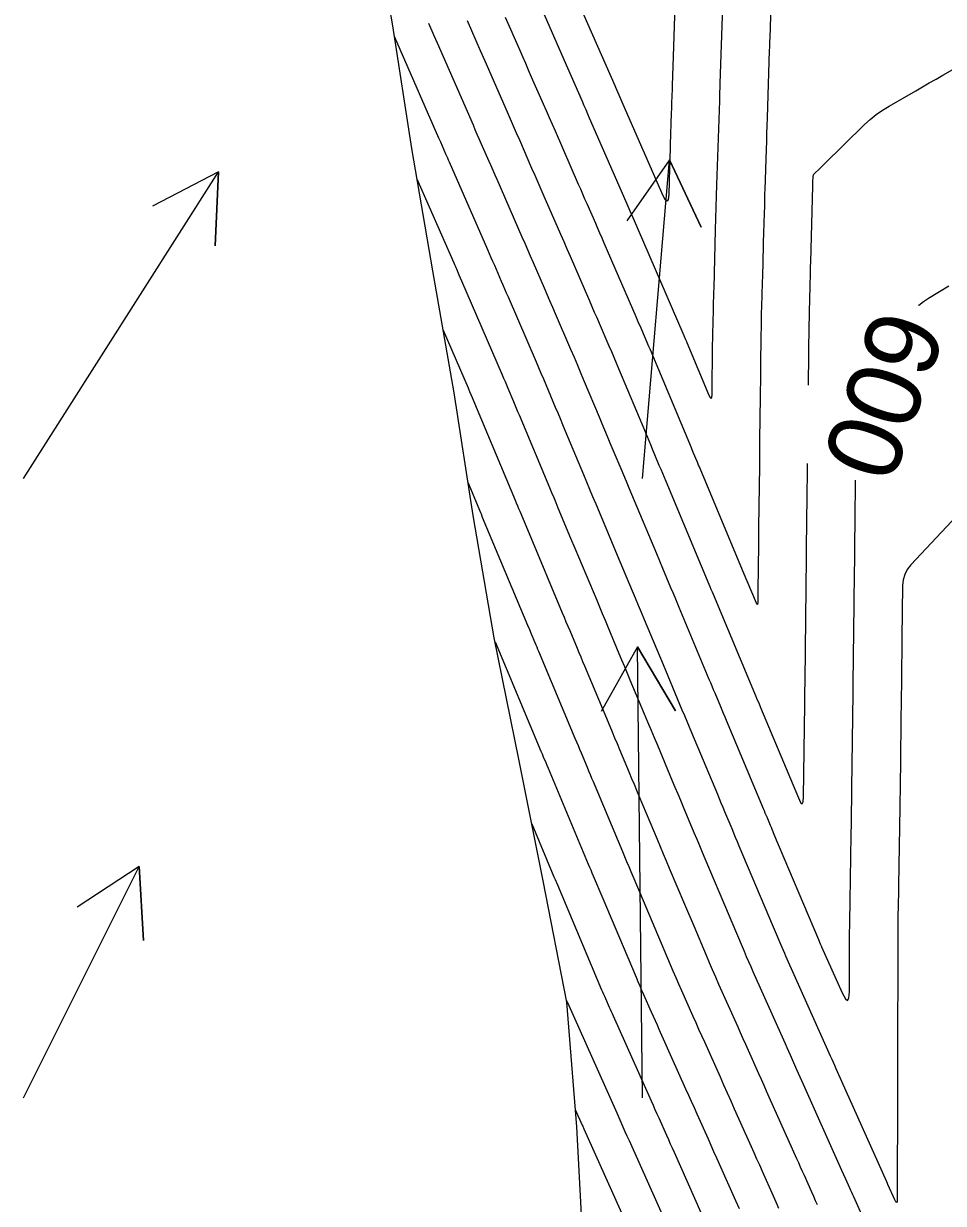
# Model space of a CAD drawing. Extents: x 954385 to 988206, y 1868364 to 1924553.
# Drawn here: x 957957.1 to 958031.4, y 1918710.4 to 1918805.7 of the extents above; entities that cross this region are included whole.
import ezdxf

# ---------------------------------------------------------------- set-up
doc = ezdxf.new("R2010")
doc.units = 0
for name, color, linetype in [('24', 7, 'Continuous'), ('26', 7, 'Continuous'), ('5', 7, 'Continuous'), ('6', 7, 'Continuous'), ('7', 7, 'Continuous')]:
    doc.layers.add(name, color=color, linetype=linetype)

msp = doc.modelspace()

# ---------------------------------------------------------------- linework, layer by layer
at = {"layer": '24'}
msp.add_lwpolyline([(958002.36, 1918706.439), (958001.804, 1918716.563), (958001.002, 1918726.632), (957999.088, 1918736.451), (957997.137, 1918746.262), (957995.151, 1918756.065), (957993.448, 1918765.931), (957991.903, 1918775.833), (957990.175, 1918785.694), (957988.49, 1918795.565), (957986.956, 1918805.469), (957985.254, 1918815.336), (957982.15, 1918824.888), (957981.062, 1918828.744), (957980.363, 1918834.736), (957977.937, 1918844.44), (957974.671, 1918853.956), (957971.691, 1918863.536)], dxfattribs=at)
at = {"layer": '26'}
for points in [[(958007.131, 1918768.928), (958009.293, 1918794.663), (958011.848, 1918789.234), (958009.293, 1918794.663), (958005.869, 1918789.736)], [(957957.131, 1918768.928), (957972.862, 1918793.705), (957972.609, 1918787.71), (957972.862, 1918793.705), (957967.544, 1918790.926)], [(958007.131, 1918718.928), (958006.723, 1918755.342), (958009.781, 1918750.18), (958006.723, 1918755.342), (958003.781, 1918750.112)], [(957957.131, 1918718.928), (957966.462, 1918737.61), (957966.824, 1918731.621), (957966.462, 1918737.61), (957961.457, 1918734.302)]]:
    msp.add_lwpolyline(points, dxfattribs=at)
at = {"layer": '6'}
for points in [[(957989.838, 1918805.686), (957990.266, 1918804.707), (957990.523, 1918804.12), (957993.431, 1918797.475), (957993.591, 1918797.11), (957993.75, 1918796.745), (957993.91, 1918796.38), (957994.07, 1918796.015), (957994.708, 1918794.555), (957994.868, 1918794.19), (957995.028, 1918793.825), (957995.188, 1918793.46), (957995.347, 1918793.095), (957997.384, 1918788.442), (957997.609, 1918787.927), (957997.834, 1918787.413), (957998.057, 1918786.898), (957998.281, 1918786.382), (957999.173, 1918784.321), (957999.396, 1918783.806), (957999.619, 1918783.291), (957999.842, 1918782.775), (958000.064, 1918782.26), (958001.316, 1918779.367), (958001.595, 1918778.719), (958001.872, 1918778.07), (958002.148, 1918777.42), (958002.422, 1918776.769), (958003.623, 1918773.902), (958003.841, 1918773.382), (958004.059, 1918772.862), (958004.277, 1918772.342), (958004.495, 1918771.822), (958005.366, 1918769.743), (958005.584, 1918769.223), (958005.801, 1918768.703), (958006.019, 1918768.183), (958006.237, 1918767.663), (958008.244, 1918762.868), (958008.737, 1918761.69), (958009.395, 1918760.12), (958009.559, 1918759.728), (958009.724, 1918759.335), (958009.888, 1918758.943), (958010.052, 1918758.55), (958012.49, 1918752.728), (958012.606, 1918752.452), (958012.722, 1918752.176), (958012.837, 1918751.9), (958012.953, 1918751.624), (958013.416, 1918750.519), (958013.532, 1918750.243), (958013.647, 1918749.967), (958013.763, 1918749.691), (958013.879, 1918749.415), (958016.87, 1918742.276), (958016.94, 1918742.108), (958017.011, 1918741.94), (958017.081, 1918741.773), (958017.151, 1918741.605), (958017.432, 1918740.934), (958017.503, 1918740.766), (958017.573, 1918740.599), (958017.644, 1918740.431), (958017.714, 1918740.264), (958021.331, 1918731.715), (958021.482, 1918731.358), (958021.508, 1918731.298), (958021.533, 1918731.239), (958021.559, 1918731.18), (958021.585, 1918731.121), (958023.254, 1918727.387), (958023.505, 1918726.913), (958023.685, 1918726.775), (958023.793, 1918726.974), (958023.831, 1918727.509), (958023.841, 1918731.38), (958023.841, 1918731.569), (958023.843, 1918731.757), (958023.845, 1918731.946), (958023.848, 1918732.134), (958023.862, 1918732.954), (958023.864, 1918733.109), (958023.867, 1918733.265), (958023.869, 1918733.421), (958023.872, 1918733.577), (958023.885, 1918734.356), (958023.89, 1918734.667), (958023.893, 1918734.823), (958023.982, 1918740.161), (958023.997, 1918741.103), (958024.011, 1918742.044), (958024.024, 1918742.986), (958024.036, 1918743.927), (958024.129, 1918751.585), (958024.136, 1918752.166), (958024.138, 1918752.343), (958024.138, 1918752.365), (958024.214, 1918758.741), (958024.218, 1918759.127), (958024.223, 1918759.512), (958024.227, 1918759.898), (958024.232, 1918760.283), (958024.268, 1918763.368), (958024.297, 1918765.809), (958024.303, 1918766.345), (958024.309, 1918766.88), (958024.315, 1918767.416), (958024.322, 1918767.951), (958024.332, 1918768.784)], [(958029.404, 1918782.901), (958029.447, 1918782.938), (958029.828, 1918783.225), (958030.23, 1918783.488), (958031.876, 1918784.488)], [(957995.217, 1918755.74), (957998.918, 1918746.911), (957999.013, 1918746.683), (957999.109, 1918746.455), (957999.3, 1918745.999), (957999.395, 1918745.771), (957999.491, 1918745.543), (958002.743, 1918737.778), (958002.84, 1918737.546), (958002.938, 1918737.315), (958003.035, 1918737.083), (958003.133, 1918736.852), (958003.916, 1918735.002), (958006.6, 1918728.657), (958006.75, 1918728.306), (958006.901, 1918727.956), (958007.053, 1918727.607), (958007.208, 1918727.259), (958007.83, 1918725.867), (958007.985, 1918725.519), (958008.141, 1918725.171), (958008.296, 1918724.823), (958008.452, 1918724.475), (958010.605, 1918719.651), (958010.831, 1918719.145), (958011.057, 1918718.639), (958011.283, 1918718.133), (958011.509, 1918717.627), (958012.414, 1918715.603), (958012.64, 1918715.097), (958012.866, 1918714.591), (958013.092, 1918714.085), (958013.318, 1918713.579), (958014.64, 1918710.621), (958014.93, 1918709.973)]]:
    msp.add_lwpolyline(points, dxfattribs=at)
at = {"layer": '7'}
for points in [[(958009.811, 1918809.565), (958009.598, 1918803.001), (958009.521, 1918800.652), (958009.509, 1918800.281), (958009.497, 1918799.91), (958009.473, 1918799.169), (958009.461, 1918798.798), (958009.449, 1918798.427), (958009.367, 1918795.907), (958009.351, 1918795.426), (958009.336, 1918794.944), (958009.32, 1918794.462), (958009.304, 1918793.981), (958009.235, 1918791.851), (958009.194, 1918791.458), (958009.106, 1918791.313), (958008.971, 1918791.415), (958008.788, 1918791.765), (958005.569, 1918799.122), (958005.404, 1918799.498), (958004.966, 1918800.501), (958004.911, 1918800.626), (958001.612, 1918808.165)], [(958017.511, 1918808.051), (958017.395, 1918804.48), (958017.387, 1918804.235), (958017.379, 1918803.991), (958017.371, 1918803.746), (958017.363, 1918803.501), (958017.185, 1918798.045), (958017.165, 1918797.411), (958017.144, 1918796.778), (958017.124, 1918796.144), (958017.103, 1918795.511), (958016.997, 1918792.249), (958016.989, 1918791.979), (958016.98, 1918791.71), (958016.972, 1918791.44), (958016.965, 1918791.171), (958016.936, 1918790.092), (958016.928, 1918789.823), (958016.921, 1918789.553), (958016.914, 1918789.284), (958016.906, 1918789.014), (958016.802, 1918785.205), (958016.792, 1918784.824), (958016.781, 1918784.444), (958016.771, 1918784.063), (958016.761, 1918783.682), (958016.719, 1918782.159), (958016.709, 1918781.778), (958016.701, 1918781.397), (958016.694, 1918781.016), (958016.689, 1918780.636), (958016.655, 1918777.856), (958016.648, 1918777.266), (958016.641, 1918776.676), (958016.634, 1918776.085), (958016.627, 1918775.495), (958016.585, 1918772.075), (958016.579, 1918771.598), (958016.574, 1918771.121), (958016.568, 1918770.643), (958016.562, 1918770.166), (958016.538, 1918768.041), (958016.533, 1918767.672), (958016.529, 1918767.302), (958016.525, 1918766.933), (958016.52, 1918766.563), (958016.503, 1918765.085), (958016.499, 1918764.715), (958016.494, 1918764.346), (958016.49, 1918763.976), (958016.486, 1918763.606), (958016.441, 1918759.895), (958016.438, 1918759.641), (958016.435, 1918759.386), (958016.429, 1918758.878), (958016.422, 1918758.781), (958016.403, 1918758.746), (958016.371, 1918758.771), (958016.328, 1918758.858), (958015.588, 1918760.625), (958015.479, 1918760.885), (958011.772, 1918769.742), (958011.714, 1918769.879), (958011.656, 1918770.017), (958011.599, 1918770.155), (958011.541, 1918770.292), (958011.253, 1918770.98), (958011.137, 1918771.255), (958011.08, 1918771.393), (958007.948, 1918778.866), (958007.839, 1918779.125), (958007.729, 1918779.385), (958007.618, 1918779.644), (958007.507, 1918779.902), (958007.06, 1918780.937), (958006.948, 1918781.195), (958006.836, 1918781.454), (958006.724, 1918781.712), (958006.612, 1918781.971), (958004.031, 1918787.935), (958003.859, 1918788.331), (958003.688, 1918788.726), (958003.515, 1918789.122), (958003.342, 1918789.517), (958002.65, 1918791.098), (958002.477, 1918791.494), (958002.304, 1918791.889), (958002.131, 1918792.284), (958001.958, 1918792.68), (958000.084, 1918796.963), (957999.844, 1918797.511), (957999.605, 1918798.059), (957999.365, 1918798.607), (957999.125, 1918799.155), (957998.166, 1918801.347), (957997.926, 1918801.895), (957997.686, 1918802.443), (957997.446, 1918802.991), (957997.206, 1918803.539), (957996.062, 1918806.154)], [(957998.875, 1918807.072), (958001.059, 1918802.083), (958001.353, 1918801.409), (958001.648, 1918800.736), (958002.237, 1918799.389), (958002.385, 1918799.052), (958002.532, 1918798.716), (958002.679, 1918798.379), (958002.827, 1918798.042), (958005.774, 1918791.305), (958005.858, 1918791.113), (958005.942, 1918790.921), (958006.026, 1918790.729), (958006.111, 1918790.537), (958006.447, 1918789.768), (958006.531, 1918789.576), (958006.615, 1918789.383), (958006.698, 1918789.191), (958006.782, 1918788.999), (958010.391, 1918780.659), (958010.471, 1918780.474), (958010.604, 1918780.166), (958010.631, 1918780.104), (958010.657, 1918780.042), (958010.684, 1918779.98), (958010.71, 1918779.918), (958012.49, 1918775.67), (958012.596, 1918775.458), (958012.672, 1918775.396), (958012.719, 1918775.482), (958012.737, 1918775.718), (958012.752, 1918776.959), (958012.756, 1918777.269), (958012.76, 1918777.579), (958012.764, 1918777.889), (958012.767, 1918778.199), (958012.787, 1918779.786), (958012.792, 1918780.154), (958012.799, 1918780.522), (958012.807, 1918780.89), (958012.816, 1918781.258), (958012.858, 1918782.807), (958012.869, 1918783.188), (958012.879, 1918783.568), (958012.889, 1918783.949), (958012.9, 1918784.33), (958013.027, 1918789.017), (958013.053, 1918789.926), (958013.079, 1918790.834), (958013.107, 1918791.742), (958013.136, 1918792.65), (958013.355, 1918799.414), (958013.372, 1918799.933), (958013.396, 1918800.654), (958013.401, 1918800.822), (958013.604, 1918807.033)], [(957992.95, 1918805.92), (957993.663, 1918804.292), (957994.019, 1918803.477), (957994.375, 1918802.663), (957996.18, 1918798.538), (957996.429, 1918797.97), (957996.677, 1918797.402), (957996.926, 1918796.834), (957997.175, 1918796.266), (957998.169, 1918793.993), (957998.417, 1918793.425), (957998.666, 1918792.857), (957998.915, 1918792.289), (957999.163, 1918791.721), (958000.238, 1918789.267), (958000.499, 1918788.668), (958000.76, 1918788.069), (958001.021, 1918787.47), (958001.28, 1918786.871), (958002.833, 1918783.283), (958003.03, 1918782.828), (958003.227, 1918782.372), (958003.424, 1918781.917), (958003.621, 1918781.461), (958004.409, 1918779.639), (958004.606, 1918779.184), (958004.801, 1918778.727), (958004.994, 1918778.27), (958005.187, 1918777.813), (958007.352, 1918772.647), (958007.489, 1918772.319), (958007.627, 1918771.99), (958007.765, 1918771.661), (958007.903, 1918771.332), (958008.453, 1918770.018), (958008.591, 1918769.689), (958008.729, 1918769.36), (958008.867, 1918769.031), (958009.004, 1918768.703), (958011.867, 1918761.865), (958012.477, 1918760.408), (958012.564, 1918760.2), (958012.651, 1918759.992), (958012.738, 1918759.784), (958012.825, 1918759.576), (958016.17, 1918751.587), (958016.251, 1918751.395), (958016.332, 1918751.202), (958016.534, 1918750.72), (958016.655, 1918750.431), (958019.712, 1918743.136), (958019.892, 1918742.774), (958020.023, 1918742.667), (958020.104, 1918742.815), (958020.135, 1918743.218), (958020.225, 1918750.666), (958020.229, 1918750.978), (958020.234, 1918751.368), (958020.235, 1918751.523), (958020.236, 1918751.601), (958020.248, 1918752.579), (958020.337, 1918760.107), (958020.347, 1918760.914), (958020.356, 1918761.721), (958020.366, 1918762.528), (958020.375, 1918763.335), (958020.424, 1918767.494), (958020.432, 1918768.178), (958020.44, 1918768.863), (958020.455, 1918770.152)], [(958020.531, 1918776.453), (958020.591, 1918781.443), (958020.597, 1918781.858), (958020.605, 1918782.273), (958020.614, 1918782.688), (958020.624, 1918783.104), (958020.669, 1918784.764), (958020.681, 1918785.179), (958020.692, 1918785.595), (958020.703, 1918786.01), (958020.715, 1918786.425), (958020.88, 1918792.521), (958020.881, 1918792.553), (958020.882, 1918792.586), (958020.883, 1918792.618), (958020.884, 1918792.651), (958020.893, 1918792.91), (958020.905, 1918793.297), (958020.914, 1918793.369), (958020.936, 1918793.436), (958020.971, 1918793.497), (958021.018, 1918793.553), (958021.412, 1918793.938), (958021.579, 1918794.102), (958021.747, 1918794.265), (958025.06, 1918797.506), (958025.518, 1918797.927), (958026.001, 1918798.317), (958026.507, 1918798.675), (958027.037, 1918799.002), (958029.205, 1918800.245), (958029.747, 1918800.556), (958030.289, 1918800.866), (958030.831, 1918801.177), (958031.373, 1918801.488), (958037.89, 1918805.224)], [(958032.523, 1918765.905), (958028.798, 1918761.954), (958028.507, 1918761.586), (958028.298, 1918761.185), (958028.171, 1918760.752), (958028.124, 1918760.286), (958028.075, 1918756.046), (958028.071, 1918755.761), (958028.068, 1918755.476), (958028.064, 1918755.191), (958028.061, 1918754.906), (958028.048, 1918753.766), (958028.044, 1918753.481), (958028.041, 1918753.197), (958028.037, 1918752.912), (958028.034, 1918752.627), (958027.994, 1918749.382), (958027.986, 1918748.746), (958027.979, 1918748.11), (958027.971, 1918747.474), (958027.963, 1918746.838), (958027.922, 1918743.461), (958027.919, 1918743.191), (958027.915, 1918742.92), (958027.911, 1918742.649), (958027.907, 1918742.379), (958027.802, 1918736.076), (958027.791, 1918735.388), (958027.779, 1918734.699), (958027.756, 1918733.322), (958027.751, 1918732.977), (958027.747, 1918732.633), (958027.744, 1918732.289), (958027.743, 1918731.944), (958027.717, 1918721.437), (958027.712, 1918719.555), (958027.711, 1918719.085), (958027.71, 1918718.614), (958027.709, 1918718.144), (958027.707, 1918717.673), (958027.694, 1918712.593), (958027.694, 1918712.359), (958027.693, 1918712.124), (958027.693, 1918711.89), (958027.692, 1918711.655), (958027.69, 1918710.714), (958027.678, 1918710.537), (958027.642, 1918710.471), (958027.582, 1918710.516), (958027.499, 1918710.674), (958026.944, 1918711.917), (958026.912, 1918711.988), (958026.848, 1918712.132), (958022.879, 1918721.016), (958022.767, 1918721.267), (958022.655, 1918721.517), (958022.431, 1918722.018), (958022.319, 1918722.269), (958022.207, 1918722.52), (958018.814, 1918730.116), (958018.71, 1918730.349), (958018.608, 1918730.583), (958018.507, 1918730.818), (958018.406, 1918731.053), (958017.71, 1918732.7), (958014.938, 1918739.252), (958014.792, 1918739.597), (958014.646, 1918739.942), (958014.501, 1918740.288), (958014.356, 1918740.633), (958013.777, 1918742.015), (958013.632, 1918742.361), (958013.488, 1918742.707), (958013.343, 1918743.052), (958013.198, 1918743.398), (958011.103, 1918748.399), (958010.912, 1918748.854), (958010.72, 1918749.31), (958010.529, 1918749.766), (958010.338, 1918750.222), (958009.574, 1918752.045), (958009.383, 1918752.501), (958009.192, 1918752.957), (958009.001, 1918753.413), (958008.81, 1918753.869), (958007.279, 1918757.524), (958007.038, 1918758.101), (958006.796, 1918758.678), (958006.555, 1918759.255), (958006.313, 1918759.832), (958005.105, 1918762.717), (958004.38, 1918764.448), (958003.372, 1918766.858), (958003.123, 1918767.452), (958002.874, 1918768.046), (958002.625, 1918768.64), (958002.376, 1918769.234), (958000.877, 1918772.814), (958000.684, 1918773.274), (958000.491, 1918773.734), (958000.298, 1918774.194), (958000.106, 1918774.654), (957999.334, 1918776.494), (957999.141, 1918776.954), (957998.946, 1918777.413), (957998.75, 1918777.872), (957998.553, 1918778.33), (957996.286, 1918783.572), (957996.148, 1918783.891), (957996.01, 1918784.209), (957995.872, 1918784.527), (957995.735, 1918784.846), (957995.183, 1918786.119), (957995.045, 1918786.438), (957994.907, 1918786.756), (957994.768, 1918787.074), (957994.629, 1918787.392), (957991.531, 1918794.47), (957991.46, 1918794.632), (957991.39, 1918794.793), (957991.319, 1918794.955), (957991.248, 1918795.117), (957990.965, 1918795.765), (957990.823, 1918796.088), (957990.681, 1918796.412), (957987.086, 1918804.628)], [(957988.907, 1918793.121), (957991.875, 1918786.342), (957991.928, 1918786.221), (957991.981, 1918786.099), (957992.033, 1918785.978), (957992.086, 1918785.856), (957992.296, 1918785.37), (957992.401, 1918785.127), (957992.507, 1918784.884), (957995.79, 1918777.293), (957995.905, 1918777.025), (957996.02, 1918776.757), (957996.134, 1918776.488), (957996.247, 1918776.22), (957996.698, 1918775.144), (957996.81, 1918774.875), (957996.923, 1918774.606), (957997.036, 1918774.337), (957997.148, 1918774.068), (957999.604, 1918768.208), (957999.775, 1918767.799), (957999.947, 1918767.389), (958000.118, 1918766.98), (958000.29, 1918766.57), (958001.318, 1918764.113), (958001.661, 1918763.294), (958003.42, 1918759.092), (958003.645, 1918758.557), (958003.869, 1918758.021), (958004.093, 1918757.486), (958004.317, 1918756.951), (958005.214, 1918754.809), (958005.438, 1918754.274), (958005.662, 1918753.739), (958005.887, 1918753.203), (958006.111, 1918752.668), (958007.261, 1918749.925), (958007.527, 1918749.289), (958007.794, 1918748.653), (958008.06, 1918748.018), (958008.326, 1918747.382), (958009.526, 1918744.519), (958009.745, 1918743.996), (958009.965, 1918743.473), (958010.184, 1918742.949), (958010.403, 1918742.426), (958011.28, 1918740.332), (958011.499, 1918739.809), (958011.719, 1918739.285), (958011.94, 1918738.763), (958012.161, 1918738.24), (958014.113, 1918733.626), (958014.635, 1918732.392), (958015.331, 1918730.748), (958015.506, 1918730.337), (958015.683, 1918729.927), (958015.862, 1918729.518), (958016.043, 1918729.11), (958018.508, 1918723.591), (958018.641, 1918723.292), (958018.775, 1918722.994), (958018.908, 1918722.696), (958019.041, 1918722.398), (958019.573, 1918721.206), (958019.706, 1918720.908), (958019.839, 1918720.61), (958019.973, 1918720.312), (958020.106, 1918720.014), (958023.205, 1918713.076), (958023.365, 1918712.72), (958023.524, 1918712.364), (958023.842, 1918711.652), (958023.921, 1918711.474), (958024.001, 1918711.296), (958024.08, 1918711.117), (958024.16, 1918710.939), (958027.83, 1918702.717)], [(957991.013, 1918780.913), (957993.027, 1918776.255), (957993.061, 1918776.178), (957993.094, 1918776.1), (957993.127, 1918776.023), (957993.16, 1918775.945), (957993.355, 1918775.478), (957993.42, 1918775.322), (957996.831, 1918767.182), (957996.925, 1918766.957), (957997.019, 1918766.732), (957997.114, 1918766.507), (957997.208, 1918766.282), (957997.962, 1918764.482), (958000.644, 1918758.076), (958000.793, 1918757.72), (958000.941, 1918757.364), (958001.09, 1918757.009), (958001.239, 1918756.653), (958001.835, 1918755.231), (958001.984, 1918754.875), (958002.133, 1918754.52), (958002.282, 1918754.164), (958002.431, 1918753.809), (958004.473, 1918748.936), (958004.67, 1918748.466), (958004.867, 1918747.997), (958005.064, 1918747.527), (958005.26, 1918747.057), (958006.048, 1918745.178), (958006.245, 1918744.708), (958006.441, 1918744.239), (958006.638, 1918743.769), (958006.835, 1918743.299), (958008.302, 1918739.796), (958008.547, 1918739.212), (958008.792, 1918738.629), (958009.038, 1918738.045), (958009.285, 1918737.462), (958010.518, 1918734.548), (958011.258, 1918732.799), (958012.255, 1918730.443), (958012.504, 1918729.856), (958012.757, 1918729.271), (958013.013, 1918728.687), (958013.271, 1918728.105), (958014.809, 1918724.662), (958015.02, 1918724.191), (958015.23, 1918723.72), (958015.44, 1918723.249), (958015.65, 1918722.778), (958016.491, 1918720.895), (958016.702, 1918720.424), (958016.912, 1918719.953), (958017.122, 1918719.482), (958017.333, 1918719.011), (958019.563, 1918714.02), (958019.714, 1918713.682), (958019.865, 1918713.344), (958020.016, 1918713.005), (958020.167, 1918712.667), (958020.772, 1918711.315), (958020.923, 1918710.977), (958021.074, 1918710.639), (958021.225, 1918710.3)], [(958018.146, 1918709.982), (958017.924, 1918710.48), (958017.701, 1918710.978), (958016.811, 1918712.971), (958016.588, 1918713.469), (958016.366, 1918713.967), (958016.143, 1918714.466), (958015.92, 1918714.964), (958014.56, 1918718.009), (958014.272, 1918718.653), (958013.985, 1918719.296), (958013.697, 1918719.94), (958013.41, 1918720.583), (958012.151, 1918723.404), (958011.918, 1918723.925), (958011.685, 1918724.445), (958011.453, 1918724.966), (958011.22, 1918725.487), (958010.29, 1918727.57), (958010.058, 1918728.091), (958009.829, 1918728.614), (958009.603, 1918729.138), (958009.38, 1918729.662), (958007.414, 1918734.308), (958006.898, 1918735.529), (958006.209, 1918737.157), (958006.037, 1918737.564), (958005.865, 1918737.972), (958005.694, 1918738.379), (958005.523, 1918738.787), (958003.163, 1918744.421), (958003.041, 1918744.713), (958002.918, 1918745.005), (958002.796, 1918745.297), (958002.674, 1918745.589), (958002.185, 1918746.756), (958002.062, 1918747.048), (958001.94, 1918747.34), (958001.818, 1918747.632), (958001.695, 1918747.924), (957998.75, 1918754.949), (957998.677, 1918755.125), (957998.603, 1918755.301), (957998.529, 1918755.477), (957998.456, 1918755.653), (957998.161, 1918756.356), (957998.014, 1918756.707), (957997.867, 1918757.059), (957994.211, 1918765.791), (957994.109, 1918766.035), (957994.058, 1918766.157), (957993.03, 1918768.611)], [(957998.176, 1918741.036), (957999.964, 1918736.769), (957999.987, 1918736.713), (958000.01, 1918736.658), (958000.034, 1918736.603), (958000.057, 1918736.547), (958000.244, 1918736.104), (958003.821, 1918727.651), (958003.896, 1918727.475), (958003.972, 1918727.299), (958004.049, 1918727.123), (958004.127, 1918726.948), (958004.44, 1918726.247), (958004.518, 1918726.072), (958004.596, 1918725.896), (958004.674, 1918725.721), (958004.753, 1918725.546), (958007.821, 1918718.674), (958007.976, 1918718.328), (958008.13, 1918717.982), (958008.285, 1918717.637), (958008.439, 1918717.291), (958009.057, 1918715.907), (958009.212, 1918715.561), (958009.366, 1918715.215), (958009.521, 1918714.869), (958009.676, 1918714.523), (958011.845, 1918709.669)], [(958000.964, 1918726.829), (958001.041, 1918726.646), (958001.045, 1918726.636), (958001.054, 1918726.617), (958005.037, 1918717.697), (958005.12, 1918717.511), (958005.203, 1918717.326), (958005.286, 1918717.14), (958005.369, 1918716.954), (958005.701, 1918716.21), (958005.867, 1918715.839), (958006.033, 1918715.467), (958009.049, 1918708.717)], [(958001.691, 1918717.976), (958002.252, 1918716.72), (958002.298, 1918716.617), (958002.39, 1918716.411), (958006.254, 1918707.765)]]:
    msp.add_lwpolyline(points, dxfattribs=at)

# ---------------------------------------------------------------- texts
at = {"layer": '5'}
msp.add_text('600', height=6, rotation=250.57316, dxfattribs=at).set_placement((958026.008, 1918782.963))

doc.saveas('drawing.dxf')
